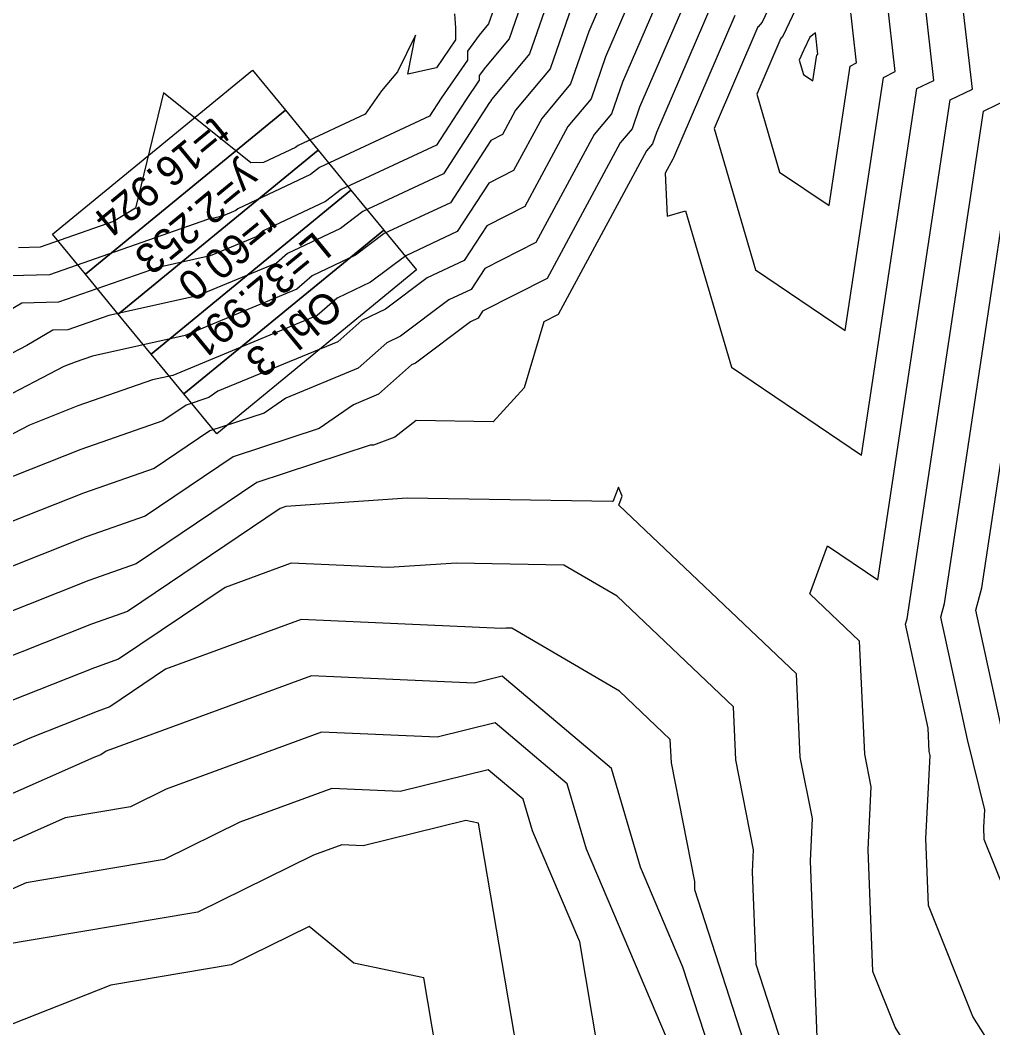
# Model space of a CAD drawing. Extents: x -549394 to -546608, y -1037055 to -1033629.
# Drawn here: x -547740.1 to -547627.3, y -1035648 to -1035531 of the extents above; entities that cross this region are included whole.
import ezdxf

# ---------------------------------------------------------------- set-up
doc = ezdxf.new("R2010")
doc.units = 0
for name, color, linetype in [('hlavni_vrst', 7, 'Continuous'), ('norm_vrst', 7, 'Continuous'), ('x_popis_oblouky_C11', 7, 'Continuous')]:
    doc.layers.add(name, color=color, linetype=linetype)

msp = doc.modelspace()

# ---------------------------------------------------------------- linework, layer by layer
at = {"layer": 'hlavni_vrst'}
for p, q in [((-547638.6, -1035537.02), (-547641.33, -1035513.01)), ((-547647.82, -1035517.94), (-547654.03, -1035531.27)), ((-547682.03, -1035520.64), (-547685.78, -1035531.46)), ((-547667.85, -1035525.24), (-547672.2, -1035535.3)), ((-547685.78, -1035531.46), (-547686.88, -1035532.78)), ((-547654.53, -1035531.83), (-547659.62, -1035543.61)), ((-547654.48, -1035531.8), (-547654.53, -1035531.83)), ((-547654.03, -1035531.27), (-547654.48, -1035531.8)), ((-547686.88, -1035532.78), (-547688.23, -1035534.65)), ((-547688.22, -1035535.67), (-547691.27, -1035540.11)), ((-547688.23, -1035534.65), (-547688.22, -1035535.67)), ((-547672.2, -1035535.3), (-547673.88, -1035540.16)), ((-547644.39, -1035567.05), (-547639.96, -1035537.69)), ((-547639.96, -1035537.69), (-547638.6, -1035537.02)), ((-547691.27, -1035540.11), (-547692.61, -1035542.19)), ((-547673.88, -1035540.16), (-547676.56, -1035543.39)), ((-547692.61, -1035542.19), (-547705.37, -1035548.14)), ((-547676.56, -1035543.39), (-547681.58, -1035552.67)), ((-547659.62, -1035543.61), (-547654.8, -1035560.01)), ((-547628.56, -1035596.95), (-547620.62, -1035544.22)), ((-547705.37, -1035548.14), (-547706.45, -1035548.95)), ((-547706.45, -1035548.95), (-547714.87, -1035552.95)), ((-547715.08, -1035553.14), (-547716.64, -1035553.78)), ((-547714.87, -1035552.95), (-547715.08, -1035553.14)), ((-547681.58, -1035552.67), (-547685.99, -1035554.91)), ((-547718.39, -1035554.17), (-547736.73, -1035560.59)), ((-547716.64, -1035553.78), (-547718.39, -1035554.17)), ((-547685.99, -1035554.91), (-547688.6, -1035558.94)), ((-547688.6, -1035558.94), (-547692.88, -1035560.94)), ((-547654.8, -1035560.01), (-547644.39, -1035567.05)), ((-547736.73, -1035560.59), (-547743.54, -1035560.76)), ((-547692.88, -1035560.94), (-547697.74, -1035564.59)), ((-547697.74, -1035564.59), (-547700.47, -1035565.89)), ((-547700.47, -1035565.89), (-547703.27, -1035568.38)), ((-547703.27, -1035568.38), (-547717.17, -1035574.12)), ((-547717.17, -1035574.12), (-547718.22, -1035574.85)), ((-547718.22, -1035574.85), (-547720.85, -1035575.72)), ((-547720.85, -1035575.72), (-547723.56, -1035577.55)), ((-547723.56, -1035577.55), (-547733.09, -1035580.87)), ((-547733.09, -1035580.87), (-547743.07, -1035584.83)), ((-547708.68, -1035594.07), (-547716.35, -1035596.89)), ((-547697.34, -1035594.58), (-547708.68, -1035594.07)), ((-547689.5, -1035594.07), (-547697.34, -1035594.58)), ((-547677.03, -1035594.3), (-547689.5, -1035594.07)), ((-547670.86, -1035597.91), (-547677.03, -1035594.3)), ((-547716.35, -1035596.89), (-547728.69, -1035605.22)), ((-547629.25, -1035599.53), (-547628.56, -1035596.95)), ((-547657.37, -1035610.73), (-547670.86, -1035597.91)), ((-547626.32, -1035613.01), (-547629.25, -1035599.53)), ((-547728.69, -1035605.22), (-547731.51, -1035606.21)), ((-547731.51, -1035606.21), (-547746.38, -1035612.11)), ((-547657.09, -1035616.91), (-547657.37, -1035610.73)), ((-547655.03, -1035627.36), (-547657.09, -1035616.91)), ((-547688.42, -1035623.94), (-547700.33, -1035626.88)), ((-547686.95, -1035624.25), (-547688.42, -1035623.94)), ((-547681.49, -1035656.31), (-547686.95, -1035624.25)), ((-547702.79, -1035626.77), (-547706.1, -1035627.98)), ((-547700.33, -1035626.88), (-547702.79, -1035626.77)), ((-547706.1, -1035627.98), (-547719.52, -1035634.57)), ((-547655.15, -1035629.91), (-547655.03, -1035627.36)), ((-547654.74, -1035640.65), (-547655.15, -1035629.91)), ((-547719.52, -1035634.57), (-547743.94, -1035638.7)), ((-547651.72, -1035649.98), (-547654.74, -1035640.65))]:
    msp.add_line(p, q, dxfattribs=at)
at = {"layer": 'norm_vrst'}
for p, q in [((-547629.65, -1035539.04), (-547634.82, -1035493.5)), ((-547634.12, -1035538.03), (-547638.07, -1035503.26)), ((-547643.08, -1035536.01), (-547644.59, -1035522.77)), ((-547680.06, -1035523.57), (-547683.4, -1035533.2)), ((-547670.52, -1035523.92), (-547674.16, -1035532.36)), ((-547648.17, -1035525.49), (-547651.59, -1035532.84)), ((-547678.1, -1035526.5), (-547681.02, -1035534.94)), ((-547665.19, -1035526.56), (-547670.23, -1035538.23)), ((-547662.52, -1035527.88), (-547668.26, -1035541.16)), ((-547676.13, -1035529.43), (-547678.64, -1035536.68)), ((-547659.86, -1035529.19), (-547666.29, -1035544.09)), ((-547689.71, -1035530.31), (-547689.6, -1035531.93)), ((-547657.2, -1035530.51), (-547664.33, -1035547.03)), ((-547689.6, -1035531.93), (-547689.6, -1035533.31)), ((-547694.26, -1035532.79), (-547696.34, -1035537.05)), ((-547695.16, -1035537.3), (-547694.26, -1035532.79)), ((-547689.6, -1035533.31), (-547691.82, -1035536.56)), ((-547683.4, -1035533.2), (-547686.14, -1035536.49)), ((-547674.16, -1035532.36), (-547676.26, -1035538.42)), ((-547651.87, -1035533.15), (-547654.67, -1035539.65)), ((-547651.84, -1035533.13), (-547651.87, -1035533.15)), ((-547651.59, -1035532.84), (-547651.84, -1035533.13)), ((-547648.51, -1035533.03), (-547649.15, -1035534.41)), ((-547647.84, -1035532.53), (-547648.51, -1035533.03)), ((-547647.56, -1035535), (-547647.84, -1035532.53)), ((-547649.2, -1035534.47), (-547649.73, -1035535.68)), ((-547649.15, -1035534.41), (-547649.2, -1035534.46)), ((-547649.2, -1035534.46), (-547649.2, -1035534.47)), ((-547681.02, -1035534.94), (-547685.4, -1035540.2)), ((-547649.73, -1035535.68), (-547649.23, -1035537.37)), ((-547648.16, -1035538.1), (-547647.7, -1035535.07)), ((-547647.7, -1035535.07), (-547647.56, -1035535)), ((-547691.82, -1035536.56), (-547695.16, -1035537.3)), ((-547686.14, -1035536.49), (-547686.85, -1035537.48)), ((-547678.64, -1035536.68), (-547682.64, -1035541.49)), ((-547646.27, -1035552.57), (-547643.83, -1035536.38)), ((-547643.83, -1035536.38), (-547643.08, -1035536.01)), ((-547696.34, -1035537.05), (-547698.18, -1035539.26)), ((-547686.85, -1035538.02), (-547688.46, -1035540.36)), ((-547686.85, -1035537.48), (-547686.85, -1035538.02)), ((-547649.23, -1035537.37), (-547648.16, -1035538.1)), ((-547636.09, -1035538.99), (-547634.12, -1035538.03)), ((-547676.26, -1035538.42), (-547679.6, -1035542.44)), ((-547670.23, -1035538.23), (-547671.5, -1035541.9)), ((-547642.5, -1035581.52), (-547636.09, -1035538.99)), ((-547632.22, -1035540.3), (-547629.65, -1035539.04)), ((-547723.49, -1035539.49), (-547726.74, -1035552.86)), ((-547713.37, -1035547.59), (-547723.49, -1035539.49)), ((-547698.18, -1035539.26), (-547700.09, -1035541.95)), ((-547688.46, -1035540.36), (-547691.81, -1035545.54)), ((-547685.47, -1035540.37), (-547685.65, -1035540.62)), ((-547685.4, -1035540.2), (-547685.48, -1035540.31)), ((-547685.48, -1035540.31), (-547685.47, -1035540.37)), ((-547654.67, -1035539.65), (-547652.02, -1035548.69)), ((-547640.62, -1035596), (-547632.22, -1035540.3)), ((-547628.35, -1035541.61), (-547625.17, -1035540.05)), ((-547685.65, -1035540.62), (-547691.01, -1035548.89)), ((-547682.64, -1035541.49), (-547684.17, -1035544.32)), ((-547668.26, -1035541.16), (-547669.12, -1035543.64)), ((-547700.09, -1035541.95), (-547707.87, -1035545.58)), ((-547679.6, -1035542.44), (-547682.88, -1035548.5)), ((-547671.5, -1035541.9), (-547673.53, -1035544.33)), ((-547637.23, -1035600.54), (-547628.35, -1035541.61)), ((-547669.12, -1035543.64), (-547670.49, -1035545.28)), ((-547632.9, -1035598.75), (-547624.49, -1035542.91)), ((-547685.52, -1035545.01), (-547690.21, -1035552.24)), ((-547684.17, -1035544.32), (-547685.52, -1035545.01)), ((-547673.53, -1035544.33), (-547680.29, -1035556.85)), ((-547666.29, -1035544.09), (-547666.74, -1035545.38)), ((-547708.19, -1035545.82), (-547711.88, -1035547.58)), ((-547707.87, -1035545.58), (-547708.19, -1035545.82)), ((-547691.81, -1035545.54), (-547702.87, -1035550.7)), ((-547670.49, -1035545.28), (-547678.99, -1035561.02)), ((-547667.45, -1035546.23), (-547677.7, -1035565.2)), ((-547666.74, -1035545.38), (-547667.45, -1035546.23)), ((-547664.41, -1035547.18), (-547665.28, -1035548.8)), ((-547664.36, -1035547.12), (-547664.41, -1035547.18)), ((-547664.33, -1035547.03), (-547664.36, -1035547.12)), ((-547711.88, -1035547.58), (-547713.37, -1035547.59)), ((-547682.88, -1035548.5), (-547685.75, -1035549.96)), ((-547691.01, -1035548.89), (-547700.37, -1035553.26)), ((-547665.28, -1035548.8), (-547665.06, -1035553.81)), ((-547652.02, -1035548.69), (-547646.27, -1035552.57)), ((-547702.87, -1035550.7), (-547704.71, -1035552.08)), ((-547685.75, -1035549.96), (-547689.4, -1035555.59)), ((-547704.71, -1035552.08), (-547711.99, -1035555.54)), ((-547726.74, -1035552.86), (-547729.27, -1035554.41)), ((-547700.37, -1035553.26), (-547702.96, -1035555.21)), ((-547690.21, -1035552.24), (-547697.87, -1035555.82)), ((-547665.06, -1035553.81), (-547662.92, -1035553.17)), ((-547662.92, -1035553.17), (-547657.59, -1035571.33)), ((-547729.27, -1035554.41), (-547737.81, -1035557.4)), ((-547711.99, -1035555.54), (-547712.72, -1035556.19)), ((-547702.96, -1035555.21), (-547709.11, -1035558.13)), ((-547689.4, -1035555.59), (-547695.38, -1035558.38)), ((-547712.72, -1035556.19), (-547718.09, -1035558.4)), ((-547697.87, -1035555.82), (-547701.22, -1035558.34)), ((-547737.81, -1035557.4), (-547740.3, -1035557.46)), ((-547680.29, -1035556.85), (-547686.22, -1035559.86)), ((-547718.09, -1035558.4), (-547724.11, -1035559.75)), ((-547709.11, -1035558.13), (-547710.36, -1035559.24)), ((-547701.22, -1035558.34), (-547706.23, -1035560.71)), ((-547695.38, -1035558.38), (-547699.48, -1035561.46)), ((-547724.11, -1035559.75), (-547735.65, -1035563.79)), ((-547710.36, -1035559.24), (-547719.53, -1035563.03)), ((-547686.22, -1035559.86), (-547687.8, -1035562.3)), ((-547706.23, -1035560.71), (-547708, -1035562.28)), ((-547678.99, -1035561.02), (-547686.46, -1035564.82)), ((-547708, -1035562.28), (-547720.97, -1035567.65)), ((-547699.48, -1035561.46), (-547703.35, -1035563.3)), ((-547687.8, -1035562.3), (-547690.38, -1035563.5)), ((-547735.65, -1035563.79), (-547739.94, -1035563.89)), ((-547719.53, -1035563.03), (-547729.82, -1035565.32)), ((-547703.35, -1035563.3), (-547705.64, -1035565.33)), ((-547690.38, -1035563.5), (-547696, -1035567.72)), ((-547739.94, -1035563.89), (-547747.21, -1035568.18)), ((-547686.46, -1035564.82), (-547687, -1035565.65)), ((-547729.82, -1035565.32), (-547734.57, -1035566.98)), ((-547705.64, -1035565.33), (-547722.42, -1035572.27)), ((-547687.88, -1035566.06), (-547694.26, -1035570.85)), ((-547687, -1035565.65), (-547687.88, -1035566.06)), ((-547679.35, -1035566.04), (-547681.63, -1035573.7)), ((-547677.7, -1035565.2), (-547679.35, -1035566.04)), ((-547736.34, -1035567.03), (-547739.33, -1035568.79)), ((-547734.57, -1035566.98), (-547736.34, -1035567.03)), ((-547720.97, -1035567.65), (-547731.73, -1035570.04)), ((-547697.59, -1035568.48), (-547700.91, -1035571.43)), ((-547696, -1035567.72), (-547697.59, -1035568.48)), ((-547739.33, -1035568.79), (-547749.1, -1035573.86)), ((-547733.72, -1035570.74), (-547735.03, -1035571.26)), ((-547731.73, -1035570.04), (-547733.72, -1035570.74)), ((-547735.03, -1035571.26), (-547750.35, -1035579.21)), ((-547700.91, -1035571.43), (-547709.31, -1035574.9)), ((-547694.71, -1035571.06), (-547698.55, -1035574.47)), ((-547694.26, -1035570.85), (-547694.71, -1035571.06)), ((-547657.59, -1035571.33), (-547642.5, -1035581.52)), ((-547724.77, -1035572.79), (-547733.41, -1035575.81)), ((-547722.42, -1035572.27), (-547724.77, -1035572.79)), ((-547681.63, -1035573.7), (-547685.25, -1035577.66)), ((-547709.31, -1035574.9), (-547711.82, -1035576.65)), ((-547698.55, -1035574.47), (-547701.46, -1035575.68)), ((-547733.41, -1035575.81), (-547739.05, -1035578.04)), ((-547711.82, -1035576.65), (-547718.13, -1035578.72)), ((-547701.46, -1035575.68), (-547705.43, -1035578.44)), ((-547694.19, -1035577.51), (-547696.64, -1035579.43)), ((-547685.25, -1035577.66), (-547694.19, -1035577.51)), ((-547739.05, -1035578.04), (-547751.6, -1035584.56)), ((-547718.13, -1035578.72), (-547724.58, -1035583.08)), ((-547705.43, -1035578.44), (-547715.4, -1035581.71)), ((-547696.64, -1035579.43), (-547699.11, -1035580.36)), ((-547699.52, -1035580.39), (-547712.67, -1035584.71)), ((-547699.11, -1035580.36), (-547699.52, -1035580.39)), ((-547715.4, -1035581.71), (-547725.61, -1035588.62)), ((-547724.58, -1035583.08), (-547732.77, -1035585.94)), ((-547712.67, -1035584.71), (-547726.64, -1035594.15)), ((-547732.77, -1035585.94), (-547747.09, -1035591.62)), ((-547670.71, -1035585.26), (-547671.25, -1035586.64)), ((-547670.29, -1035586.31), (-547670.71, -1035585.26)), ((-547695.23, -1035586.53), (-547709.31, -1035587.5)), ((-547695.23, -1035586.53), (-547695.23, -1035586.53)), ((-547695.23, -1035586.53), (-547695.23, -1035586.53)), ((-547671.39, -1035586.93), (-547695.23, -1035586.53)), ((-547695.23, -1035586.53), (-547695.23, -1035586.53)), ((-547695.23, -1035586.53), (-547695.23, -1035586.53)), ((-547671.32, -1035586.86), (-547671.39, -1035586.93)), ((-547671.25, -1035586.64), (-547671.32, -1035586.86)), ((-547670.67, -1035587.33), (-547670.29, -1035586.31)), ((-547709.94, -1035587.71), (-547727.66, -1035599.69)), ((-547709.31, -1035587.5), (-547709.94, -1035587.71)), ((-547650.05, -1035606.93), (-547670.67, -1035587.33)), ((-547725.61, -1035588.62), (-547732.46, -1035591.01)), ((-547732.46, -1035591.01), (-547751.11, -1035598.41)), ((-547648.52, -1035597.62), (-547646.45, -1035592.06)), ((-547646.45, -1035592.06), (-547640.62, -1035596)), ((-547726.64, -1035594.15), (-547732.14, -1035596.08)), ((-547732.14, -1035596.08), (-547755.13, -1035605.19)), ((-547642.73, -1035603.12), (-547648.52, -1035597.62)), ((-547633.32, -1035600.34), (-547632.9, -1035598.75)), ((-547727.66, -1035599.69), (-547731.82, -1035601.14)), ((-547731.82, -1035601.14), (-547753.78, -1035609.85)), ((-547707.5, -1035600.61), (-547723.25, -1035606.39)), ((-547684.22, -1035601.65), (-547707.5, -1035600.61)), ((-547637.4, -1035601.15), (-547637.23, -1035600.54)), ((-547634.77, -1035613.21), (-547637.4, -1035601.15)), ((-547630.23, -1035614.55), (-547633.32, -1035600.34)), ((-547683.77, -1035601.62), (-547684.22, -1035601.65)), ((-547683.07, -1035601.63), (-547683.77, -1035601.62)), ((-547670.6, -1035608.91), (-547683.07, -1035601.63)), ((-547642.13, -1035616.25), (-547642.73, -1035603.12)), ((-547723.25, -1035606.39), (-547729.71, -1035610.76)), ((-547649.61, -1035616.58), (-547650.05, -1035606.93)), ((-547706.32, -1035607.15), (-547730.15, -1035615.9)), ((-547687.46, -1035607.99), (-547706.32, -1035607.15)), ((-547684.19, -1035607.18), (-547687.46, -1035607.99)), ((-547671.53, -1035617.89), (-547684.19, -1035607.18)), ((-547664.69, -1035614.53), (-547670.6, -1035608.91)), ((-547731.19, -1035611.28), (-547738.98, -1035614.37)), ((-547729.71, -1035610.76), (-547731.19, -1035611.28)), ((-547685, -1035612.62), (-547691.75, -1035614.28)), ((-547676.64, -1035619.69), (-547685, -1035612.62)), ((-547705.15, -1035613.69), (-547723.16, -1035620.3)), ((-547691.75, -1035614.28), (-547705.15, -1035613.69)), ((-547634.65, -1035615.92), (-547634.77, -1035613.21)), ((-547738.98, -1035614.37), (-547752.87, -1035620.52)), ((-547664.57, -1035617.24), (-547664.69, -1035614.53)), ((-547628.22, -1035622.7), (-547630.23, -1035614.55)), ((-547730.87, -1035616.34), (-547731.58, -1035616.62)), ((-547730.74, -1035616.3), (-547730.87, -1035616.34)), ((-547730.15, -1035615.9), (-547730.74, -1035616.3)), ((-547641.38, -1035620.04), (-547642.13, -1035616.25)), ((-547635.03, -1035626.03), (-547634.56, -1035616.38)), ((-547634.56, -1035616.38), (-547634.65, -1035615.92)), ((-547731.58, -1035616.62), (-547751.1, -1035625.27)), ((-547661.85, -1035631.02), (-547664.57, -1035617.24)), ((-547648.2, -1035623.7), (-547649.61, -1035616.58)), ((-547685.81, -1035618.06), (-547696.04, -1035620.58)), ((-547681.76, -1035621.48), (-547685.81, -1035618.06)), ((-547668.16, -1035629.37), (-547671.53, -1035617.89)), ((-547674.42, -1035627.26), (-547676.64, -1035619.69)), ((-547723.16, -1035620.3), (-547727.33, -1035622.35)), ((-547703.97, -1035620.23), (-547714.63, -1035624.14)), ((-547696.04, -1035620.58), (-547703.97, -1035620.23)), ((-547641.73, -1035627.32), (-547641.38, -1035620.04)), ((-547680.68, -1035625.15), (-547681.76, -1035621.48)), ((-547727.33, -1035622.35), (-547734.91, -1035623.63)), ((-547628.32, -1035624.73), (-547628.22, -1035622.7)), ((-547734.91, -1035623.63), (-547749.32, -1035630.02)), ((-547714.63, -1035624.14), (-547723.42, -1035628.46)), ((-547648.44, -1035628.62), (-547648.2, -1035623.7)), ((-547675.2, -1035638.01), (-547680.68, -1035625.15)), ((-547628.26, -1035626.14), (-547628.32, -1035624.73)), ((-547634.73, -1035633.8), (-547635.03, -1035626.03)), ((-547620.57, -1035645.42), (-547628.26, -1035626.14)), ((-547664.12, -1035651.44), (-547674.42, -1035627.26)), ((-547641.19, -1035641.47), (-547641.73, -1035627.32)), ((-547723.42, -1035628.46), (-547739.42, -1035631.17)), ((-547647.66, -1035649.13), (-547648.44, -1035628.62)), ((-547663.22, -1035640.95), (-547668.16, -1035629.37)), ((-547739.42, -1035631.17), (-547747.54, -1035634.76)), ((-547661.86, -1035631.21), (-547661.85, -1035631.02)), ((-547661.83, -1035632), (-547661.86, -1035631.21)), ((-547655.76, -1035650.76), (-547661.83, -1035632)), ((-547629.59, -1035646.68), (-547634.73, -1035633.8)), ((-547706.57, -1035636.24), (-547715.62, -1035640.68)), ((-547701.39, -1035640.49), (-547706.57, -1035636.24)), ((-547672.44, -1035654.25), (-547675.2, -1035638.01)), ((-547715.62, -1035640.68), (-547729.59, -1035643.04)), ((-547693.3, -1035642.18), (-547701.39, -1035640.49)), ((-547659.8, -1035651.53), (-547663.22, -1035640.95)), ((-547638.61, -1035647.94), (-547641.19, -1035641.47)), ((-547729.59, -1035643.04), (-547742.66, -1035648.19)), ((-547690.54, -1035658.37), (-547693.3, -1035642.18)), ((-547625.63, -1035652.96), (-547629.59, -1035646.68)), ((-547631.93, -1035658.52), (-547638.61, -1035647.94))]:
    msp.add_line(p, q, dxfattribs=at)
at = {"layer": 'x_popis_oblouky_C11'}
for points in [[(-547709.35, -1035541.49), (-547732.54, -1035560.52), (-547736.35, -1035555.88), (-547713.16, -1035536.85)], [(-547705.54, -1035546.13), (-547728.73, -1035565.16), (-547732.54, -1035560.52), (-547709.35, -1035541.49)], [(-547701.74, -1035550.76), (-547724.93, -1035569.8), (-547728.73, -1035565.16), (-547705.54, -1035546.13)], [(-547697.93, -1035555.4), (-547721.12, -1035574.43), (-547724.93, -1035569.8), (-547701.74, -1035550.76)], [(-547694.12, -1035560.04), (-547717.31, -1035579.07), (-547721.12, -1035574.43), (-547697.93, -1035555.4)]]:
    msp.add_lwpolyline(points, close=True, dxfattribs=at)

# ---------------------------------------------------------------- texts
for s, p in [('t=16.924', (-547717.64, -1035542.09)), ('y=2.253', (-547714.15, -1035547.44)), ('r=60.0', (-547711.79, -1035552.7)), ('L=32.991', (-547705.93, -1035555.43)), ('Obl. 3', (-547704.6, -1035562.1))]:
    msp.add_text(s, height=3.5, rotation=219.4003, dxfattribs=at).set_placement(p)

doc.saveas('drawing.dxf')
